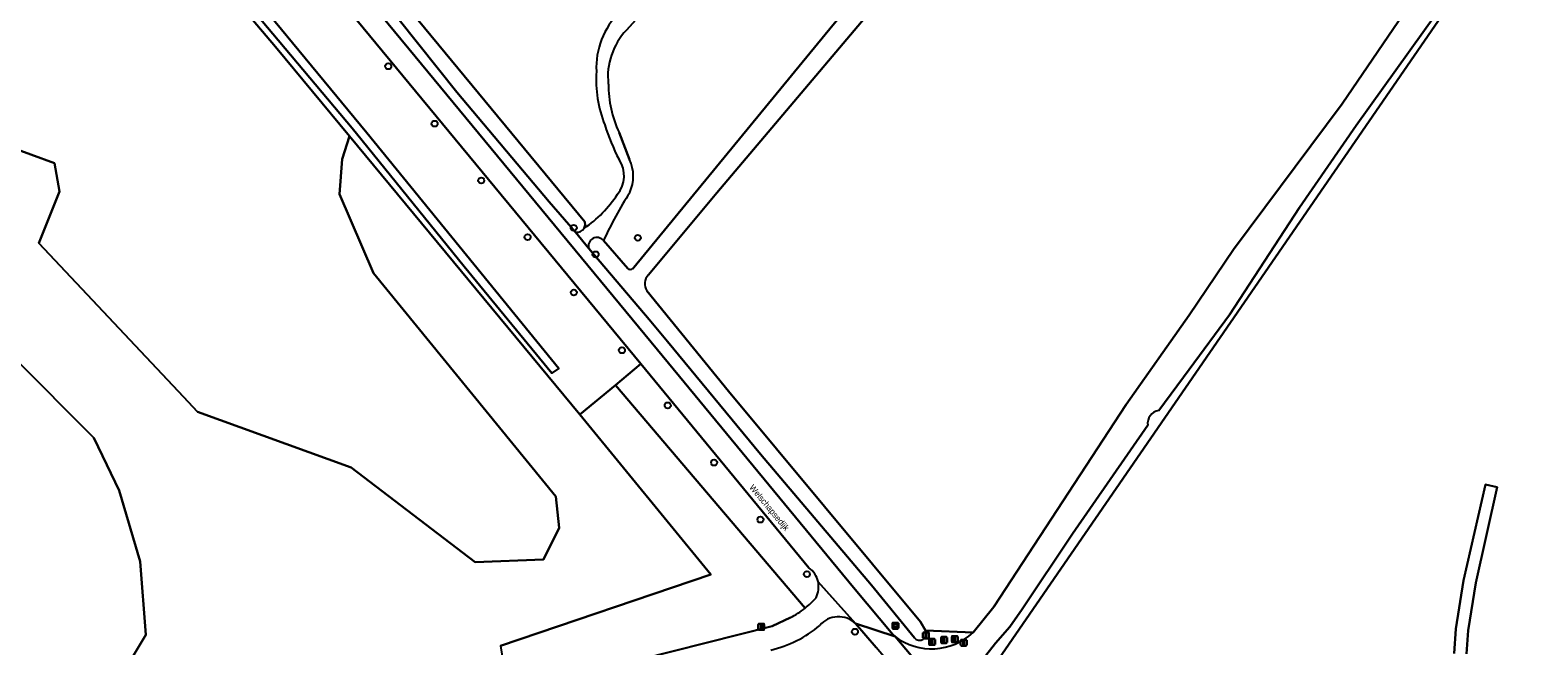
# Model space of a CAD drawing. Extents: x 156061 to 157804, y 383437 to 385640.
# Drawn here: x 156810.9 to 157056.9, y 384634.6 to 384735.1 of the extents above; entities that cross this region are included whole.
import ezdxf

# ---------------------------------------------------------------- set-up
doc = ezdxf.new("R2010")
doc.units = 0
for name, color, linetype in [('IMGEO_Afsluitpaal', 7, 'Continuous'), ('IMGEO_Berm_groen', 7, 'Continuous'), ('IMGEO_Boom', 7, 'Continuous'), ('IMGEO_Fietspad_gesloten', 7, 'Continuous'), ('IMGEO_Gemengd_bos', 7, 'Continuous'), ('IMGEO_Grasland_overig', 7, 'Continuous'), ('IMGEO_Groenvoorziening', 7, 'Continuous'), ('IMGEO_Hek', 7, 'Continuous'), ('IMGEO_Lichtmast', 7, 'Continuous'), ('IMGEO_Loofbos', 7, 'Continuous'), ('IMGEO_Openbare_ruimte_label', 7, 'Continuous'), ('IMGEO_Waterloop', 7, 'Continuous'), ('IMGEO_Wegwijzer', 7, 'Continuous')]:
    doc.layers.add(name, color=color, linetype=linetype)

msp = doc.modelspace()

# ---------------------------------------------------------------- linework, layer by layer
at = {"layer": 'IMGEO_Afsluitpaal'}
for p, q in [((156956.55, 384635.9), (156956.55, 384636.7)), ((156956.55, 384636.7), (156956.55, 384635.9)), ((156956.65, 384636.8), (156957.44, 384636.8)), ((156957.44, 384636.8), (156956.65, 384636.8)), ((156957.54, 384636.7), (156957.54, 384635.9)), ((156957.54, 384635.9), (156957.54, 384636.7)), ((156961.26, 384635.29), (156961.26, 384636.09)), ((156961.26, 384636.09), (156961.26, 384635.29)), ((156961.36, 384636.19), (156962.15, 384636.19)), ((156962.15, 384636.19), (156961.36, 384636.19)), ((156962.25, 384636.09), (156962.25, 384635.29)), ((156962.25, 384635.29), (156962.25, 384636.09)), ((156957.44, 384635.8), (156956.65, 384635.8)), ((156956.65, 384635.8), (156957.44, 384635.8)), ((156957.57, 384634.84), (156957.57, 384635.64)), ((156957.57, 384635.64), (156957.57, 384634.84)), ((156957.67, 384635.74), (156958.46, 384635.74)), ((156958.46, 384635.74), (156957.67, 384635.74)), ((156958.46, 384634.74), (156957.67, 384634.74)), ((156957.67, 384634.74), (156958.46, 384634.74)), ((156958.56, 384635.64), (156958.56, 384634.84)), ((156958.56, 384634.84), (156958.56, 384635.64)), ((156959.52, 384635.15), (156959.52, 384635.95)), ((156959.52, 384635.95), (156959.52, 384635.15)), ((156959.62, 384636.05), (156960.41, 384636.05)), ((156960.41, 384636.05), (156959.62, 384636.05)), ((156960.41, 384635.05), (156959.62, 384635.05)), ((156959.62, 384635.05), (156960.41, 384635.05)), ((156960.51, 384635.95), (156960.51, 384635.15)), ((156960.51, 384635.15), (156960.51, 384635.95)), ((156962.15, 384635.19), (156961.36, 384635.19)), ((156961.36, 384635.19), (156962.15, 384635.19)), ((156962.72, 384634.71), (156962.72, 384635.5)), ((156962.72, 384635.5), (156962.72, 384634.71)), ((156962.82, 384635.6), (156963.61, 384635.6)), ((156963.61, 384635.6), (156962.82, 384635.6)), ((156963.61, 384634.61), (156962.82, 384634.61)), ((156962.82, 384634.61), (156963.61, 384634.61)), ((156963.71, 384635.5), (156963.71, 384634.71)), ((156963.71, 384634.71), (156963.71, 384635.5))]:
    msp.add_line(p, q, dxfattribs=at)
for points in [[(156956.97, 384636.67), (156957.12, 384636.67), (156957.12, 384635.92), (156956.97, 384635.92), (156956.97, 384636.67)], [(156961.68, 384636.07), (156961.83, 384636.07), (156961.83, 384635.32), (156961.68, 384635.32), (156961.68, 384636.07)], [(156957.99, 384635.62), (156958.14, 384635.62), (156958.14, 384634.87), (156957.99, 384634.87), (156957.99, 384635.62)], [(156959.94, 384635.92), (156960.09, 384635.92), (156960.09, 384635.17), (156959.94, 384635.17), (156959.94, 384635.92)], [(156963.14, 384635.48), (156963.29, 384635.48), (156963.29, 384634.73), (156963.14, 384634.73), (156963.14, 384635.48)]]:
    msp.add_lwpolyline(points, dxfattribs=at)
for centre, start, end in [((156956.65, 384636.7), 90, 180), ((156956.65, 384636.7), 90, 180), ((156957.44, 384636.7), 0, 90), ((156957.44, 384636.7), 360, 90), ((156961.36, 384636.09), 90, 180), ((156961.36, 384636.09), 90, 180), ((156962.15, 384636.09), 0, 90), ((156962.15, 384636.09), 360, 90), ((156956.65, 384635.9), 180, 270), ((156956.65, 384635.9), 180, 270), ((156957.44, 384635.9), 270, 0), ((156957.44, 384635.9), 270, 0), ((156957.67, 384635.64), 90, 180), ((156957.67, 384635.64), 90, 180), ((156957.67, 384634.84), 180, 270), ((156957.67, 384634.84), 180, 270), ((156958.46, 384635.64), 0, 90), ((156958.46, 384635.64), 360, 90), ((156958.46, 384634.84), 270, 0), ((156958.46, 384634.84), 270, 0), ((156959.62, 384635.95), 90, 180), ((156959.62, 384635.95), 90, 180), ((156959.62, 384635.15), 180, 270), ((156959.62, 384635.15), 180, 270), ((156960.41, 384635.95), 0, 90), ((156960.41, 384635.95), 360, 90), ((156960.41, 384635.15), 270, 0), ((156960.41, 384635.15), 270, 0), ((156961.36, 384635.29), 180, 270), ((156961.36, 384635.29), 180, 270), ((156962.15, 384635.29), 270, 0), ((156962.15, 384635.29), 270, 0), ((156962.82, 384635.5), 90, 180), ((156962.82, 384635.5), 90, 180), ((156962.82, 384634.71), 180, 270), ((156962.82, 384634.71), 180, 270), ((156963.61, 384635.5), 0, 90), ((156963.61, 384635.5), 360, 90), ((156963.61, 384634.71), 270, 0), ((156963.61, 384634.71), 270, 0)]:
    msp.add_arc(centre, 0.1, start, end, dxfattribs=at)
at = {"layer": 'IMGEO_Berm_groen'}
for points in [[(156600.26, 385062.64), (156611.41, 385049.1), (156616.13, 385043.37), (156628.31, 385028.6), (156628.66, 385028.19), (156634.53, 385021.05), (156651.9, 385000), (156717.24, 384920.7), (156766.23, 384861.24), (156857.95, 384750), (156913.26, 384682.92), (156945.25, 384644.12), (156951.65, 384636.45), (156952.01, 384636.1)], [(156911.88, 384687.9), (156902.04, 384699.49), (156899.9, 384702.15), (156895.57, 384707.11), (156880.52, 384724.99), (156871.1, 384736.8), (156860.19, 384750), (156840.15, 384774.25), (156828.52, 384788.04)], [(156955.17, 384635.88), (156948.15, 384644.48), (156930.08, 384665.91), (156914.88, 384684.27), (156911.88, 384687.9)], [(156910.52, 384680.62), (156906.38, 384677.17), (156937.33, 384640.75)], [(156937.97, 384647.33), (156910.52, 384680.62)], [(157000, 384574.89), (156992.9, 384582.99), (156977.24, 384601.18), (156966.54, 384613.57), (156956.8, 384625), (156948.92, 384634.34), (156945.58, 384638.24)], [(156964.76, 384636.78), (156956.99, 384637.11)]]:
    msp.add_lwpolyline(points, dxfattribs=at)
for centre, radius, start, end in [((156935.65, 384644.19), 3.9, 13.3731, 53.5565), ((156935.66, 384644.2), 3.89, 333.0449, 13.3681), ((156928.05, 384652.4), 14.9, 308.5495, 318.0269), ((156942.8, 384635.34), 4.01, 46.2254, 139.9072), ((156927.2, 384652.9), 19.53, 283.3871, 309.9373), ((156957.98, 384644.09), 9.97, 233.2442, 312.8511), ((156956.01, 384636.6), 1.11, 220.6341, 27.2814)]:
    msp.add_arc(centre, radius, start, end, dxfattribs=at)
at = {"layer": 'IMGEO_Boom'}
for centre in [(156869.33, 384729.23), (156876.89, 384719.86), (156884.49, 384710.59), (156899.59, 384702.86), (156892.06, 384701.33), (156910.04, 384701.23), (156903.16, 384698.52), (156899.6, 384692.28), (156907.46, 384682.86), (156914.92, 384673.86), (156922.49, 384664.52), (156930.05, 384655.21), (156937.63, 384646.3), (156945.48, 384636.9)]:
    msp.add_circle(centre, 0.489, dxfattribs=at)
at = {"layer": 'IMGEO_Fietspad_gesloten'}
for points in [[(156913.26, 384682.92), (156857.95, 384750), (156766.23, 384861.24), (156717.24, 384920.7), (156651.9, 385000), (156634.53, 385021.05), (156628.66, 385028.19), (156628.31, 385028.6), (156616.13, 385043.37), (156611.41, 385049.1), (156600.26, 385062.64)], [(156605.09, 385050.03), (156608.82, 385046.51), (156609.37, 385045.98), (156609.93, 385045.44), (156647.34, 385000), (156714.45, 384918.5), (156763.61, 384858.81), (156853.32, 384750), (156910.52, 384680.62), (156937.97, 384647.33)], [(156939.44, 384645.1), (156945.58, 384638.24), (156952.01, 384636.1), (156951.65, 384636.45), (156945.25, 384644.12), (156913.26, 384682.92)], [(156945.58, 384638.24), (156939.44, 384645.1)], [(156934.94, 384639.2), (156931.97, 384637.82), (156888.89, 384626.92), (156886.5, 384626.31), (156885.81, 384626.14)], [(156960.39, 384626.17), (156952.01, 384636.1), (156945.58, 384638.24), (156948.92, 384634.34)]]:
    msp.add_lwpolyline(points, dxfattribs=at)
for centre, radius, start, end in [((156935.65, 384644.19), 3.9, 13.3731, 53.5565), ((156935.66, 384644.2), 3.89, 333.0449, 13.3681), ((156928.05, 384652.4), 14.9, 308.5495, 318.0269), ((156928.18, 384652.24), 14.69, 297.4079, 308.5455), ((156942.8, 384635.34), 4.01, 46.2254, 139.9072), ((156927.2, 384652.9), 19.53, 283.3871, 309.9373)]:
    msp.add_arc(centre, radius, start, end, dxfattribs=at)
at = {"layer": 'IMGEO_Gemengd_bos'}
for points in [[(156909.41, 384696.38), (156941.87, 384735.94), (156953.6, 384750), (156967.04, 384766.13), (156980.7, 384781.58)], [(156912.63, 384740.14), (156908.19, 384735.13)], [(156887.64, 384634.58), (156921.96, 384646.24), (156900.59, 384672.36), (156863, 384717.8), (156861.8, 384714.05), (156861.35, 384708.33), (156866.93, 384695.43), (156896.68, 384658.99), (156897.2, 384653.87), (156894.67, 384648.67), (156883.49, 384648.27), (156863.25, 384663.73), (156838.21, 384672.8), (156835.91, 384675.25), (156812.3, 384700.37), (156815.65, 384708.76), (156814.85, 384713.42), (156807.13, 384716.22)], [(156906.98, 384718.4), (156908.69, 384714.03)], [(156904.43, 384700.78), (156908.42, 384696.19)], [(156808.2, 384681.7), (156821.27, 384668.56), (156823.39, 384664.13), (156825.41, 384659.94), (156828.83, 384648.36), (156829.78, 384636.4), (156821.01, 384621.8)]]:
    msp.add_lwpolyline(points, dxfattribs=at)
for centre, radius, start, end in [((156916.17, 384727.55), 11.01, 136.4739, 186.3634), ((156923.86, 384726.27), 18.62, 179.8157, 205.0017), ((156902.85, 384711.28), 6.45, 335.3938, 25.1966), ((156970.38, 384669.75), 72.88, 147.7934, 154.8019), ((156908.82, 384696.78), 0.709, 235.7789, 326.0137)]:
    msp.add_arc(centre, radius, start, end, dxfattribs=at)
at = {"layer": 'IMGEO_Grasland_overig'}
for points in [[(156995.06, 384673.02), (157000, 384679.72), (157006.58, 384688.65), (157018, 384706.19), (157027.27, 384719.55), (157049, 384750), (157049.73, 384751.02), (157051.71, 384756.32), (157067.45, 384779.73), (157078.82, 384797.04), (157111.19, 384845.3), (157125.06, 384865.65), (157130.13, 384872.27), (157130.21, 384872.37), (157130.3, 384872.46), (157130.39, 384872.55), (157127.2, 384874.52), (157122.9, 384877.49)], [(157047.44, 384756.19), (157043.24, 384750), (157025, 384723.12), (157007.27, 384699.31), (157000, 384688.61), (156989.71, 384674.03), (156968.13, 384640.98), (156964.76, 384636.78)], [(156908.19, 384735.13), (156912.63, 384740.14)], [(156908.69, 384714.03), (156906.98, 384718.4)], [(156899.9, 384702.15), (156902.04, 384699.49)], [(156964.63, 384630.23), (156968.41, 384635.04), (156970.77, 384637.72), (156972.78, 384640.58), (156980.96, 384652.91), (156993.25, 384670.61)], [(157045.25, 384633.28), (157045.52, 384637.12), (157046.76, 384644.91), (157050.29, 384660.49), (157048.34, 384660.93), (157044.79, 384645.29), (157043.53, 384637.35), (157043.26, 384633.37)], [(156952.01, 384636.1), (156960.39, 384626.17), (156971.95, 384612.68), (156983.28, 384599.59)]]:
    msp.add_lwpolyline(points, dxfattribs=at)
for centre, radius, start, end in [((156916.16, 384728.98), 12.89, 135.5682, 182.6039), ((156916.17, 384727.55), 11.01, 136.4739, 186.3634), ((156923.09, 384727.06), 19.85, 176.1201, 201.885), ((156923.86, 384726.27), 18.62, 179.8157, 205.0017), ((156939.03, 384730.36), 35.99, 197.295, 207.0582), ((156903.1, 384711.32), 4.71, 320.4606, 34.4427), ((156902.85, 384711.28), 6.45, 335.3938, 25.1966), ((156889.74, 384719.54), 20.36, 304.5519, 326.5832), ((156970.38, 384669.75), 72.88, 147.7934, 154.8019), ((156900.17, 384703.41), 1.29, 257.867, 330.2723), ((156903.37, 384699.88), 1.39, 40.2824, 196.1053), ((156995.39, 384670.88), 2.16, 98.7591, 187.3492), ((156957.98, 384644.09), 9.97, 233.2442, 312.8511)]:
    msp.add_arc(centre, radius, start, end, dxfattribs=at)
at = {"layer": 'IMGEO_Groenvoorziening'}
for points in [[(156704.18, 384910.35), (156719.79, 384891.58), (156738.88, 384868.16), (156800.19, 384793.8), (156826.08, 384762.21), (156836.09, 384750), (156844.21, 384740.36), (156850.94, 384732.38), (156863, 384717.8), (156900.59, 384672.36), (156906.38, 384677.17), (156910.52, 384680.62), (156853.32, 384750), (156763.61, 384858.81), (156714.45, 384918.5)], [(157234.91, 384629.94), (157303.66, 384667.61), (157371.16, 384705.26), (157367.35, 384708.05), (157326.25, 384739.94), (157313.23, 384749.93), (157303.32, 384757.71), (157295.82, 384763.35), (157287.05, 384770.29), (157276.64, 384778.16), (157269.81, 384782.99), (157251.08, 384794.79), (157235.56, 384804.72), (157179.95, 384839.58), (157158.87, 384852.91), (157148.97, 384858.97), (157139.5, 384863.28), (157133.04, 384863.79), (157129.5, 384863.26), (157126.71, 384861.14), (157124.21, 384858.2), (157109.09, 384836.1), (156966.05, 384628.27)], [(156966.05, 384628.27), (157109.09, 384836.1)], [(156807.13, 384716.22), (156814.85, 384713.42), (156815.65, 384708.76), (156812.3, 384700.37), (156835.91, 384675.25), (156838.21, 384672.8), (156863.25, 384663.73), (156883.49, 384648.27), (156894.67, 384648.67), (156897.2, 384653.87), (156896.68, 384658.99), (156866.93, 384695.43), (156861.35, 384708.33), (156861.8, 384714.05), (156863, 384717.8), (156850.94, 384732.38), (156844.21, 384740.36), (156836.09, 384750), (156826.08, 384762.21), (156800.19, 384793.8)], [(156982.6, 384779.99), (156976.6, 384772.41), (156957.89, 384750), (156922.91, 384708.59), (156911.79, 384695.16)], [(157067.45, 384779.73), (157051.71, 384756.32), (157049.73, 384751.02), (157049, 384750), (157027.27, 384719.55), (157018, 384706.19), (157006.58, 384688.65), (157000, 384679.72), (156995.06, 384673.02)], [(156911.52, 384692.57), (156924.85, 384676.2), (156956.19, 384638.52), (156956.99, 384637.11), (156964.76, 384636.78), (156968.13, 384640.98), (156989.71, 384674.03), (157000, 384688.61), (157007.27, 384699.31), (157025, 384723.12), (157043.24, 384750), (157047.44, 384756.19)], [(156821.01, 384621.8), (156829.78, 384636.4), (156828.83, 384648.36), (156825.41, 384659.94), (156823.39, 384664.13), (156821.27, 384668.56), (156808.2, 384681.7)], [(156993.25, 384670.61), (156980.96, 384652.91), (156972.78, 384640.58), (156970.77, 384637.72), (156968.41, 384635.04), (156964.63, 384630.23)], [(157043.26, 384633.37), (157043.53, 384637.35), (157044.79, 384645.29), (157048.34, 384660.93), (157050.29, 384660.49), (157046.76, 384644.91), (157045.52, 384637.12), (157045.25, 384633.28)]]:
    msp.add_lwpolyline(points, dxfattribs=at)
msp.add_lwpolyline([(156837.54, 384750), (156837.41, 384750.16), (156838.16, 384750.79), (156838.72, 384751.26), (156839.75, 384750), (156865.85, 384718.39), (156897.15, 384679.89), (156896, 384679.11), (156881.71, 384696.52), (156865.07, 384717.11), (156863.41, 384719.1)], close=True, dxfattribs=at)
for centre, radius, start, end in [((156913.17, 384693.71), 2.01, 133.6096, 214.5842), ((156995.39, 384670.88), 2.16, 98.7591, 187.3492)]:
    msp.add_arc(centre, radius, start, end, dxfattribs=at)
at = {"layer": 'IMGEO_Hek'}
msp.add_lwpolyline([(156979.27, 384612.75), (156966.05, 384628.27), (157109.09, 384836.1)], dxfattribs=at)
at = {"layer": 'IMGEO_Lichtmast'}
for p, q in [((156929.69, 384637.3), (156929.69, 384638.1)), ((156929.69, 384638.1), (156929.69, 384637.3)), ((156929.79, 384638.2), (156930.57, 384638.2)), ((156930.57, 384638.2), (156929.79, 384638.2)), ((156930.57, 384637.2), (156929.79, 384637.2)), ((156929.79, 384637.2), (156930.57, 384637.2)), ((156930.67, 384638.1), (156930.67, 384637.3)), ((156930.67, 384637.3), (156930.67, 384638.1))]:
    msp.add_line(p, q, dxfattribs=at)
msp.add_lwpolyline([(156930.1, 384638.07), (156930.26, 384638.07), (156930.26, 384637.32), (156930.1, 384637.32), (156930.1, 384638.07)], dxfattribs=at)
for centre, start, end in [((156929.79, 384638.1), 90, 180), ((156929.79, 384638.1), 90, 180), ((156929.79, 384637.3), 180, 270), ((156929.79, 384637.3), 180, 270), ((156930.57, 384638.1), 0, 90), ((156930.57, 384638.1), 360, 90), ((156930.57, 384637.3), 270, 0), ((156930.57, 384637.3), 270, 0)]:
    msp.add_arc(centre, 0.1, start, end, dxfattribs=at)
at = {"layer": 'IMGEO_Loofbos'}
for points in [[(156830.46, 384789.83), (156839.16, 384779.55), (156863.3, 384750), (156901.39, 384703.81), (156901.45, 384703.28), (156901.29, 384702.77)], [(156937.33, 384640.75), (156906.38, 384677.17), (156900.59, 384672.36), (156921.96, 384646.24), (156887.64, 384634.58), (156888.89, 384626.92), (156931.97, 384637.82), (156934.94, 384639.2)]]:
    msp.add_lwpolyline(points, dxfattribs=at)
for centre, radius, start, end in [((156916.16, 384728.98), 12.89, 135.5682, 182.6039), ((156923.09, 384727.06), 19.85, 176.1201, 201.885), ((156939.03, 384730.36), 35.99, 197.295, 207.0582), ((156903.1, 384711.32), 4.71, 320.4606, 34.4427), ((156889.74, 384719.54), 20.36, 304.5519, 326.5832), ((156928.18, 384652.24), 14.69, 297.4079, 308.5455)]:
    msp.add_arc(centre, radius, start, end, dxfattribs=at)
at = {"layer": 'IMGEO_Waterloop'}
for points in [[(156828.52, 384788.04), (156840.15, 384774.25), (156860.19, 384750), (156871.1, 384736.8), (156880.52, 384724.99), (156895.57, 384707.11), (156899.9, 384702.15)], [(156980.7, 384781.58), (156967.04, 384766.13), (156953.6, 384750), (156941.87, 384735.94), (156909.41, 384696.38)], [(156901.29, 384702.77), (156901.45, 384703.28), (156901.39, 384703.81), (156863.3, 384750)], [(156911.79, 384695.16), (156922.91, 384708.59), (156957.89, 384750)], [(156908.42, 384696.19), (156904.43, 384700.78)], [(156902.04, 384699.49), (156911.88, 384687.9), (156914.88, 384684.27), (156930.08, 384665.91), (156948.15, 384644.48), (156955.17, 384635.88)], [(156956.99, 384637.11), (156956.19, 384638.52), (156924.85, 384676.2), (156911.52, 384692.57)]]:
    msp.add_lwpolyline(points, dxfattribs=at)
msp.add_lwpolyline([(156837.41, 384750.16), (156837.54, 384750), (156863.41, 384719.1), (156865.07, 384717.11), (156881.71, 384696.52), (156896, 384679.11), (156897.15, 384679.89), (156865.85, 384718.39), (156839.75, 384750), (156838.72, 384751.26), (156838.16, 384750.79)], close=True, dxfattribs=at)
for centre, radius, start, end in [((156900.17, 384703.41), 1.29, 257.867, 330.2723), ((156903.37, 384699.88), 1.39, 40.2824, 196.1053), ((156908.82, 384696.78), 0.709, 235.7789, 326.0137), ((156913.17, 384693.71), 2.01, 133.6096, 214.5842), ((156956.01, 384636.6), 1.11, 220.6341, 27.2814)]:
    msp.add_arc(centre, radius, start, end, dxfattribs=at)
at = {"layer": 'IMGEO_Wegwijzer'}
for p, q in [((156951.58, 384637.48), (156951.58, 384638.28)), ((156951.58, 384638.28), (156951.58, 384637.48)), ((156951.68, 384638.38), (156952.47, 384638.38)), ((156952.47, 384638.38), (156951.68, 384638.38)), ((156952.47, 384637.38), (156951.68, 384637.38)), ((156951.68, 384637.38), (156952.47, 384637.38)), ((156952.57, 384638.28), (156952.57, 384637.48)), ((156952.57, 384637.48), (156952.57, 384638.28))]:
    msp.add_line(p, q, dxfattribs=at)
for points in [[(156951.68, 384638.12), (156952.47, 384638.12), (156952.47, 384637.65), (156951.68, 384637.65), (156951.68, 384638.12)], [(156951.75, 384638.05), (156951.75, 384637.72), (156952.4, 384637.72), (156952.4, 384638.05), (156951.75, 384638.05)]]:
    msp.add_lwpolyline(points, dxfattribs=at)
for centre, start, end in [((156951.68, 384638.28), 90, 180), ((156951.68, 384638.28), 90, 180), ((156951.68, 384637.48), 180, 270), ((156951.68, 384637.48), 180, 270), ((156952.47, 384638.28), 0, 90), ((156952.47, 384638.28), 360, 90), ((156952.47, 384637.48), 270, 0), ((156952.47, 384637.48), 270, 0)]:
    msp.add_arc(centre, 0.1, start, end, dxfattribs=at)

# ---------------------------------------------------------------- texts
at = {"layer": 'IMGEO_Openbare_ruimte_label'}
msp.add_text('Welschapsedijk', height=1, rotation=309.5635, dxfattribs=at).set_placement((156928.16, 384660.43))

doc.saveas('drawing.dxf')
